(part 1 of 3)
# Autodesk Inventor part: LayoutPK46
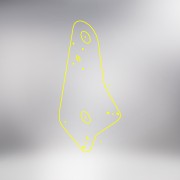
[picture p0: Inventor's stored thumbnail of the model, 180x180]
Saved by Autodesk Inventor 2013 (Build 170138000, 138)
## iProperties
Created: 2012-02
Part Number: LayoutPK46
Material: Generic
Document SubType Name: Modeling
Designer: Daniel Graham
Density: 1 g/cm^3
Author: Daniel Graham
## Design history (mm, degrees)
node "Blocks"
  sketch "_Closed"
    geometry: L1 (-25.4, 4.233)-(0, 0); L2 (0, 0)-(-25.4, -4.233); L3 (-25.4, 4.233)-(-25.4, -4.233); L4 (0, 0)-(-25.4, 0); 1 further point
    constraints: 8 end point, 1 midpoint, 1 perpendicular
  sketch "DatumFilled45"
    geometry: L1 (0, 25.4)-(0, -25.4); L2 (0, -25.4)-(-25.4, 0); L3 (-25.4, 0)-(0, 25.4); L4 (0, 25.4)-(0, -25.4); L5 (0, -25.4)-(0, 25.4); L6 (0, 25.4)-(-25.4, 0); L7 (-25.4, 0)-(0, 25.4); 1 further point
    constraints: 14 end point, 1 perpendicular
  sketch "Filled-1"
    geometry: L1 (-25.4, 0)-(0, 0); L2 (-25.4, -2.527)-(0, 0); L3 (0, 0)-(-25.4, 2.527); L4 (-25.4, 2.527)-(-25.4, -2.527); L5 (-25.4, -2.527)-(0, 0); L6 (0, 0)-(-25.4, -2.527); L7 (-25.4, -2.527)-(-25.4, 2.527); L8 (-25.4, 2.527)-(-25.4, -2.527); L9 (-25.4, -2.527)-(0, 0); L10 (0, 0)-(-25.4, 2.527); L11 (-25.4, 2.527)-(-25.4, -2.527); 1 further point
    constraints: 22 end point, 4 midpoint, 1 perpendicular
  sketch "Borders Default Border"
    geometry: L1 (19.05, 12.7)-(19.05, 419.1); L2 (19.05, 419.1)-(539.75, 419.1); L3 (539.75, 419.1)-(539.75, 12.7); L4 (539.75, 12.7)-(19.05, 12.7); L5 (279.4, 6.35)-(279.4, 12.7); L6 (279.4, 12.7)-(277.2, 8.89); L7 (277.2, 8.89)-(281.6, 8.89); L8 (281.6, 8.89)-(279.4, 12.7); L9 (279.4, 425.45)-(279.4, 419.1); L10 (279.4, 419.1)-(277.2, 422.91); L11 (277.2, 422.91)-(281.6, 422.91); L12 (281.6, 422.91)-(279.4, 419.1); L13 (12.7, 215.9)-(19.05, 215.9); L14 (19.05, 215.9)-(15.24, 218.1); L15 (15.24, 218.1)-(15.24, 213.7); L16 (15.24, 213.7)-(19.05, 215.9); L17 (546.1, 215.9)-(539.75, 215.9); L18 (539.75, 215.9)-(543.56, 218.1); L19 (543.56, 218.1)-(543.56, 213.7); L20 (543.56, 213.7)-(539.75, 215.9); L21 (139.7, 12.7)-(139.7, 8.636); L22 (139.7, 419.1)-(139.7, 423.164); L23 (419.1, 12.7)-(419.1, 8.636); L24 (419.1, 419.1)-(419.1, 423.164); L25 (19.05, 107.95)-(14.986, 107.95); L26 (539.75, 107.95)-(543.814, 107.95); L27 (19.05, 323.85)-(14.986, 323.85); L28 (539.75, 323.85)-(543.814, 323.85); 17 further points
    constraints: 56 end point, 14 parallel, 11 perpendicular, 8 point on line, 4 midpoint, 16 other
  sketch "GENAXEH"
    geometry: L1 (-25.4, 0)-(25.4, 0); 1 further point
    constraints: 2 end point
  sketch "Weldment"
    geometry: L1 (-362.49, 605.558)-(-187.308, 59.988); L2 (-48.402, -559.479)-(-89.17, -792.346); L3 (104.596, -840)-(155.018, -682.036); L4 (176.996, -25.915)-(5.037, 246.17); L5 (5.037, 246.17)-(-175.085, 674.867); L6 (-187.308, 59.988)-(-152.339, -48.916); L7 (-104.241, -121.383)-(-75.352, -146.192); L8 (-8.649, -332.41)-(-48.402, -559.479); L9 (155.018, -682.036)-(230.654, -445.083); L10 (-57.997, -88.254)-(-54.949, -85.206); L11 (-57.997, -85.206)-(-54.949, -88.254); C1 r 75 at (0, 0); C2 r 87 at (0, 0); C3 r 45 at (-267.278, 636.131); C4 r 45 at (9.332, -809.591); C5 r 1.524 at (-56.473, -86.73); A1 r 100 centre (-267.278, 636.131) between (-175.085, 674.867) and (-362.49, 605.558); A2 r 100 centre (9.332, -809.591) between (-89.17, -792.346) and (104.596, -840); A3 r 500 centre (-245.668, -293.04) between (250.28, -356.567) and (176.996, -25.915); A4 r 160 centre (0, 0) between (-152.339, -48.916) and (-104.241, -121.383); A5 r 200 centre (-205.653, -297.921) between (-8.649, -332.41) and (-75.352, -146.192); A6 r 500 centre (-245.668, -293.04) between (230.654, -445.083) and (250.28, -356.567); 1 further point
    constraints: 22 end point, 14 tangent, 12 point on circle, 11 centre point, 4 concentric, 3 equal radius, 1 perpendicular
  sketch "Connector"
    geometry: L1 (157.164, 27.531)-(232.989, 74.957); L2 (483.604, 231.708)-(512.662, 249.882); L3 (76.449, -64.463)-(145.454, 17.372); L4 (449.028, 351.621)-(398.755, 320.177); L5 (509.104, 419.139)-(460.738, 361.78); L6 (526.921, 255.966)-(571.21, 267.162); L7 (232.989, 74.957)-(483.604, 231.708); L8 (398.755, 320.177)-(93.53, 129.27); L9 (529.743, 443.615)-(509.104, 419.139); L10 (79.271, 123.186)-(-24.509, 96.95); L11 (571.21, 267.162)-(630.701, 282.202); L12 (302.321, 205.82)-(305.369, 208.868); L13 (302.321, 208.868)-(305.369, 205.82); C1 r 45 at (0, 0); C2 r 45 at (606.192, 379.152); C3 r 1.524 at (303.845, 207.344); A1 r 50 centre (539.176, 207.491) between (526.921, 255.966) and (512.662, 249.882); A2 r 50 centre (183.678, -14.86) between (157.164, 27.531) and (145.454, 17.372); A3 r 50 centre (422.514, 394.012) between (449.028, 351.621) and (460.738, 361.78); A4 r 50 centre (67.016, 171.661) between (79.271, 123.186) and (93.53, 129.27); A5 r 100 centre (606.192, 379.152) between (630.701, 282.202) and (529.743, 443.615); A6 r 100 centre (0, 0) between (-24.509, 96.95) and (76.449, -64.463); 1 further point
    constraints: 26 end point, 16 tangent, 12 point on circle, 9 centre point, 5 equal radius, 3 parallel, 2 concentric, 1 collinear, 1 perpendicular
  sketch "Base"
    geometry: L1 (278.529, -481.687)-(299.453, -447.453); L2 (295.917, -416.857)-(172.052, -291.319); L3 (95.022, -681.286)-(272.857, -489.184); L4 (108.329, 19.101)-(158.403, -264.884); L5 (-225.117, -660.979)-(-108.413, 18.617); L6 (-225.235, -722.613)-(-225.117, -660.979); L7 (-198.661, -766.881)-(-24.713, -859.13); L8 (3.19, -856.093)-(33.762, -830.109); L9 (48.097, -808.832)-(84.242, -699.551); L10 (37.419, -377.546)-(40.467, -374.498); L11 (37.419, -374.498)-(40.467, -377.546); C1 r 40 at (0, -600); C2 r 40 at (0, 0); C3 r 1.524 at (38.943, -376.022); A1 r 47.5 centre (238, -456.916) between (272.857, -489.184) and (278.529, -481.687); A2 r 25 centre (278.122, -434.416) between (299.453, -447.453) and (295.917, -416.857); A3 r 50 centre (207.644, -256.202) between (158.403, -264.884) and (172.052, -291.319); A4 r 50 centre (-175.235, -722.709) between (-225.235, -722.613) and (-198.661, -766.881); A5 r 50 centre (131.713, -715.252) between (95.022, -681.286) and (84.242, -699.551); A6 r 110 centre (0, 0) between (108.329, 19.101) and (-108.413, 18.617); A7 r 25 centre (-13, -837.043) between (-24.713, -859.13) and (3.19, -856.093); A8 r 47.5 centre (3, -793.916) between (33.762, -830.109) and (48.097, -808.832); 1 further point
    constraints: 22 end point, 16 point on circle, 16 tangent, 11 centre point, 5 equal radius, 1 concentric, 1 perpendicular
  sketch "CenterSpan"
    geometry: L1 (273.969, -185.044)-(234.974, -284.945); L2 (36.362, 93.155)-(259.933, 5.887); L3 (12.317, -103.462)-(-16.542, -98.622); L4 (180.829, -183.299)-(-38.18, -97.812); L5 (437.598, -26.22)-(296.603, -162.709); L6 (-23.266, 102.39)-(214.339, 156.38); L7 (495.815, 30.136)-(437.598, -26.22); L8 (214.339, 156.38)-(404.104, 199.5); L9 (110.262, -93.996)-(113.31, -90.948); L10 (110.262, -90.948)-(113.31, -93.996); C1 r 82 at (0, 0); C2 r 82 at (223.572, -87.267); C3 r 50 at (426.262, 101.986); C4 r 58.472 at (158.121, -254.946); C5 r 1.524 at (111.786, -92.472); A1 r 90 centre (-2.571, -192.223) between (81.268, -224.948) and (12.317, -103.462); A2 r 60 centre (329.862, -206.861) between (290.003, -162.013) and (273.969, -185.044); A3 r 100 centre (223.572, -87.267) between (290.003, -162.013) and (259.933, 5.887); A4 r 100 centre (0, 0) between (36.362, 93.155) and (-16.542, -98.622); A5 r 105 centre (223.572, -87.267) between (189.942, -186.736) and (296.603, -162.709); A6 r 105 centre (0, 0) between (-23.266, 102.39) and (-38.18, -97.812); A7 r 100 centre (426.262, 101.986) between (495.815, 30.136) and (404.104, 199.5); A8 r 82.5 centre (158.121, -254.946) between (81.268, -224.948) and (234.974, -284.945); 1 further point
    constraints: 20 end point, 17 point on circle, 15 tangent, 13 centre point, 6 concentric, 3 equal radius, 3 perpendicular, 1 collinear, 1 point on line
  sketch "Arm"
    geometry: L1 (-25.496, -107.005)-(137.409, -145.82); L2 (2597.068, -901.099)-(2521.421, -896.025); L3 (2257.231, -771.408)-(2076.35, -579.673); L4 (2076.35, -579.673)-(2063.205, -583.463); L5 (2043.846, -578.704)-(1704.981, -254.849); L6 (1379.251, -95.221)-(16.283, 108.788); L7 (137.409, -145.82)-(1374.243, -440.518); L8 (1601.431, -691.827)-(2199.578, -1052.198); L9 (2469.644, -1123.775)-(2592.355, -1120.82); L10 (1293.329, -509.09)-(1296.377, -506.042); L11 (1293.329, -506.042)-(1296.377, -509.09); C1 r 40.528 at (0, 0); C2 r 40.528 at (2589.706, -1010.852); C3 r 1.524 at (1294.853, -507.566); A1 r 400 centre (2548.19, -496.921) between (2482.623, -891.511) and (2521.421, -896.025); A2 r 110 centre (2589.706, -1010.852) between (2597.994, -1120.539) and (2597.068, -901.099); A3 r 400 centre (2548.19, -496.921) between (2257.231, -771.408) and (2482.623, -891.511); A4 r 20 centre (2057.664, -564.246) between (2043.846, -578.704) and (2063.205, -583.463); A5 r 600 centre (1290.432, -688.61) between (1704.981, -254.849) and (1379.251, -95.221); A6 r 70 centre (1358.018, -508.612) between (1423.227, -534.065) and (1374.243, -440.518); A7 r 100 centre (1516.382, -570.427) between (1423.227, -534.065) and (1519.438, -670.38); A8 r 150 centre (1524.023, -820.31) between (1601.431, -691.827) and (1519.438, -670.38); A9 r 500 centre (2457.606, -623.92) between (2199.578, -1052.198) and (2469.644, -1123.775); A10 r 110 centre (0, 0) between (16.283, 108.788) and (-25.496, -107.005); 1 further point
    constraints: 22 end point, 20 point on circle, 17 tangent, 13 centre point, 3 concentric, 2 equal radius, 1 collinear, 1 perpendicular
  sketch "Bucket"
    geometry: 1 further point
  sketch "FrontBucket"
    geometry: L1 (36.508, 713.207)-(-16.797, 670.2); L2 (-16.797, 670.2)-(-101.739, 335.484); L3 (-101.739, 335.484)-(-109.966, 2.719); L4 (8.288, -109.687)-(308.835, -86.978); L5 (308.835, -86.978)-(319.542, -83.051); L6 (19.324, 520.756)-(99.155, 741.781); L7 (99.155, 741.781)-(80.344, 748.575); L8 (80.344, 748.575)-(36.508, 713.207); L9 (1233.625, 258.517)-(1200.234, 261.682); L10 (1200.234, 261.682)-(1143.868, 239.874); L11 (1143.868, 239.874)-(1177.667, 236.867); L12 (1177.667, 236.867)-(1233.625, 258.517); L13 (967.076, 171.475)-(1143.868, 239.874); L14 (1181.276, 227.541)-(976.097, 148.159); L15 (976.097, 148.159)-(967.076, 171.475); L16 (1237.234, 249.191)-(1233.625, 258.517); L17 (1177.667, 236.867)-(1181.276, 227.541); L18 (1181.276, 227.541)-(1237.234, 249.191); L19 (332.219, -99.88)-(327.869, -88.635); L20 (332.219, -99.88)-(340.093, -96.834); L21 (327.869, -88.635)-(326.446, -84.958); L22 (630.662, 15.585)-(695.946, 40.843); L23 (340.093, -96.834)-(630.662, 15.585); L24 (971.406, 160.283)-(964.544, 144.762); L25 (971.406, 160.283)-(969.963, 164.014); L26 (695.946, 40.843)-(690.173, 55.765); L27 (969.963, 164.014)-(690.173, 55.765); L28 (695.946, 40.843)-(964.544, 144.762); L29 (271.723, 1081.905)-(246.908, 1104.472); L30 (246.908, 1104.472)-(15.69, 814.708); L31 (11.012, 759.335)-(43.462, 700.624); L32 (47.21, 660.849)-(-0.759, 514.651); L33 (556.412, -14.214)-(696.307, 39.911); L34 (696.307, 39.911)-(695.946, 40.843); L35 (594.585, 649.257)-(271.723, 1081.905); L36 (459.694, 596.673)-(459.353, 596.937); L37 (459.353, 596.937)-(498.23, 611.978); L38 (1112.062, 227.901)-(576.694, 642.28); L39 (995.062, 182.294)-(998.041, 183.455); L40 (499.228, 612.083)-(459.694, 596.673); L41 (459.694, 596.673)-(526.939, 544.624); L42 (606.946, 482.699)-(686.952, 420.773); L43 (766.958, 358.848)-(846.965, 296.922); L44 (926.971, 234.997)-(985.819, 189.448); L45 (995.055, 182.3)-(995.062, 182.294); L46 (998.041, 183.455)-(1130.882, 235.237); L47 (985.819, 189.448)-(995.055, 182.3); L48 (1130.882, 235.237)-(595.514, 649.616); C1 r 60 at (0, 0); C2 r 85 at (-189.66, 366.918); C3 r 25 at (54.772, 783.522); C4 r 62.5 at (-189.66, 366.918); A1 r 110 centre (0, 0) between (-109.966, 2.719) and (8.288, -109.687); A2 r 408 centre (403.06, 382.155) between (19.324, 520.756) and (16.94, 513.969); A3 r 50 centre (54.772, 783.522) between (15.69, 814.708) and (11.012, 759.335); A4 r 50 centre (-0.298, 676.437) between (47.21, 660.849) and (43.462, 700.624); A5 r 425 centre (403.06, 382.155) between (-0.759, 514.651) and (556.412, -14.214); 1 further point
    constraints: 96 end point, 17 parallel, 12 tangent, 10 point on circle, 9 centre point, 7 collinear, 6 perpendicular, 6 point on line, 4 concentric, 1 equal radius
  sketch "Borders Default Border_9.00X"
    geometry: L1 (171.45, 114.3)-(171.45, 3771.9); L2 (171.45, 3771.9)-(4857.749, 3771.9); L3 (4857.749, 3771.9)-(4857.749, 114.3); L4 (4857.749, 114.3)-(171.45, 114.3); L5 (2514.6, 57.15)-(2514.6, 114.3); L6 (2514.6, 114.3)-(2494.803, 80.01); L7 (2494.803, 80.01)-(2534.397, 80.01); L8 (2534.397, 80.01)-(2514.6, 114.3); L9 (2514.6, 3829.05)-(2514.6, 3771.9); L10 (2514.6, 3771.9)-(2494.803, 3806.19); L11 (2494.803, 3806.19)-(2534.397, 3806.19); L12 (2534.397, 3806.19)-(2514.6, 3771.9); L13 (114.3, 1943.1)-(171.45, 1943.1); L14 (171.45, 1943.1)-(137.16, 1962.897); L15 (137.16, 1962.897)-(137.16, 1923.303); L16 (137.16, 1923.303)-(171.45, 1943.1); L17 (4914.9, 1943.099)-(4857.749, 1943.099); L18 (4857.749, 1943.099)-(4892.04, 1962.897); L19 (4892.04, 1962.897)-(4892.04, 1923.302); L20 (4892.04, 1923.302)-(4857.749, 1943.099); L21 (1257.3, 114.3)-(1257.3, 77.724); L22 (1257.3, 3771.9)-(1257.3, 3808.476); L23 (3771.9, 114.3)-(3771.9, 77.724); L24 (3771.9, 3771.9)-(3771.9, 3808.476); L25 (171.45, 971.55)-(134.874, 971.55); L26 (4857.749, 971.549)-(4894.326, 971.549); L27 (171.45, 2914.65)-(134.874, 2914.65); L28 (4857.749, 2914.649)-(4894.326, 2914.649); 17 further points
    constraints: 56 end point, 14 parallel, 11 perpendicular, 8 point on line, 4 midpoint, 16 other
  sketch "_Closed_1"
    geometry: L1 (-25.4, 4.233)-(0, 0); L2 (0, 0)-(-25.4, -4.233); L3 (-25.4, 4.233)-(-25.4, -4.233); L4 (0, 0)-(-25.4, 0); 1 further point
    constraints: 8 end point, 1 midpoint
  sketch "DatumFilled45_1"
    geometry: L1 (0, 25.4)-(0, -25.4); L2 (0, -25.4)-(-25.4, 0); L3 (-25.4, 0)-(0, 25.4); L4 (0, 25.4)-(0, -25.4); L5 (0, -25.4)-(0, 25.4); L6 (0, 25.4)-(-25.4, 0); L7 (-25.4, 0)-(0, 25.4); 1 further point
    constraints: 14 end point
  sketch "Filled-1_1"
    geometry: L1 (-25.4, 0)-(0, 0); L2 (-25.4, -2.527)-(0, 0); L3 (0, 0)-(-25.4, 2.527); L4 (-25.4, 2.527)-(-25.4, -2.527); L5 (-25.4, -2.527)-(0, 0); L6 (0, 0)-(-25.4, -2.527); L7 (-25.4, -2.527)-(-25.4, 2.527); L8 (-25.4, 2.527)-(-25.4, -2.527); L9 (-25.4, -2.527)-(0, 0); L10 (0, 0)-(-25.4, 2.527); L11 (-25.4, 2.527)-(-25.4, -2.527); 1 further point
    constraints: 22 end point, 4 midpoint
  sketch "Borders Default Border_1"
    geometry: L1 (19.05, 12.7)-(19.05, 419.1); L2 (19.05, 419.1)-(539.75, 419.1); L3 (539.75, 419.1)-(539.75, 12.7); L4 (539.75, 12.7)-(19.05, 12.7); L5 (279.4, 6.35)-(279.4, 12.7); L6 (279.4, 12.7)-(277.2, 8.89); L7 (277.2, 8.89)-(281.6, 8.89); L8 (281.6, 8.89)-(279.4, 12.7); L9 (279.4, 425.45)-(279.4, 419.1); L10 (279.4, 419.1)-(277.2, 422.91); L11 (277.2, 422.91)-(281.6, 422.91); L12 (281.6, 422.91)-(279.4, 419.1); L13 (12.7, 215.9)-(19.05, 215.9); L14 (19.05, 215.9)-(15.24, 218.1); L15 (15.24, 218.1)-(15.24, 213.7); L16 (15.24, 213.7)-(19.05, 215.9); L17 (546.1, 215.9)-(539.75, 215.9); L18 (539.75, 215.9)-(543.56, 218.1); L19 (543.56, 218.1)-(543.56, 213.7); L20 (543.56, 213.7)-(539.75, 215.9); L21 (139.7, 12.7)-(139.7, 8.636); L22 (139.7, 419.1)-(139.7, 423.164); L23 (419.1, 12.7)-(419.1, 8.636); L24 (419.1, 419.1)-(419.1, 423.164); L25 (19.05, 107.95)-(14.986, 107.95); L26 (539.75, 107.95)-(543.814, 107.95); L27 (19.05, 323.85)-(14.986, 323.85); L28 (539.75, 323.85)-(543.814, 323.85); 17 further points
    constraints: 56 end point, 8 point on line, 4 midpoint, 16 other
  sketch "GENAXEH_1"
    geometry: L1 (-25.4, 0)-(25.4, 0); 1 further point
    constraints: 2 end point
  sketch "Weldment_1"
    geometry: L1 (-362.49, 605.558)-(-187.308, 59.988); L2 (-48.402, -559.479)-(-89.17, -792.346); L3 (104.596, -840)-(155.018, -682.036); L4 (176.996, -25.915)-(5.037, 246.17); L5 (5.037, 246.17)-(-175.085, 674.867); L6 (-187.308, 59.988)-(-152.339, -48.916); L7 (-104.241, -121.383)-(-75.352, -146.192); L8 (-8.649, -332.41)-(-48.402, -559.479); L9 (155.018, -682.036)-(230.654, -445.083); L10 (-57.997, -88.254)-(-54.949, -85.206); L11 (-57.997, -85.206)-(-54.949, -88.254); C1 r 75 at (0, 0); C2 r 87 at (0, 0); C3 r 45 at (-267.278, 636.131); C4 r 45 at (9.332, -809.591); C5 r 1.524 at (-56.473, -86.73); A1 r 100 centre (-267.278, 636.131) between (-175.085, 674.867) and (-362.49, 605.558); A2 r 100 centre (9.332, -809.591) between (-89.17, -792.346) and (104.596, -840); A3 r 500 centre (-245.668, -293.04) between (250.28, -356.567) and (176.996, -25.915); A4 r 160 centre (0, 0) between (-152.339, -48.916) and (-104.241, -121.383); A5 r 200 centre (-205.653, -297.921) between (-8.649, -332.41) and (-75.352, -146.192); A6 r 500 centre (-245.668, -293.04) between (230.654, -445.083) and (250.28, -356.567); 1 further point
    constraints: 22 end point, 12 point on circle, 11 centre point
  sketch "Connector_1"
    geometry: L1 (157.164, 27.531)-(232.989, 74.957); L2 (483.604, 231.708)-(512.662, 249.882); L3 (76.449, -64.463)-(145.454, 17.372); L4 (449.028, 351.621)-(398.755, 320.177); L5 (509.104, 419.139)-(460.738, 361.78); L6 (526.921, 255.966)-(571.21, 267.162); L7 (232.989, 74.957)-(483.604, 231.708); L8 (398.755, 320.177)-(93.53, 129.27); L9 (529.743, 443.615)-(509.104, 419.139); L10 (79.271, 123.186)-(-24.509, 96.95); L11 (571.21, 267.162)-(630.701, 282.202); L12 (302.321, 205.82)-(305.369, 208.868); L13 (302.321, 208.868)-(305.369, 205.82); C1 r 45 at (0, 0); C2 r 45 at (606.192, 379.152); C3 r 1.524 at (303.845, 207.344); A1 r 50 centre (539.176, 207.491) between (526.921, 255.966) and (512.662, 249.882); A2 r 50 centre (183.678, -14.86) between (157.164, 27.531) and (145.454, 17.372); A3 r 50 centre (422.514, 394.012) between (449.028, 351.621) and (460.738, 361.78); A4 r 50 centre (67.016, 171.661) between (79.271, 123.186) and (93.53, 129.27); A5 r 100 centre (606.192, 379.152) between (630.701, 282.202) and (529.743, 443.615); A6 r 100 centre (0, 0) between (-24.509, 96.95) and (76.449, -64.463); 1 further point
    constraints: 26 end point, 12 point on circle, 9 centre point
  sketch "Base_1"
    geometry: L1 (278.529, -481.687)-(299.453, -447.453); L2 (295.917, -416.857)-(172.052, -291.319); L3 (95.022, -681.286)-(272.857, -489.184); L4 (108.329, 19.101)-(158.403, -264.884); L5 (-225.117, -660.979)-(-108.413, 18.617); L6 (-225.235, -722.613)-(-225.117, -660.979); L7 (-198.661, -766.881)-(-24.713, -859.13); L8 (3.19, -856.093)-(33.762, -830.109); L9 (48.097, -808.832)-(84.242, -699.551); L10 (37.419, -377.546)-(40.467, -374.498); L11 (37.419, -374.498)-(40.467, -377.546); C1 r 40 at (0, -600); C2 r 40 at (0, 0); C3 r 1.524 at (38.943, -376.022); A1 r 47.5 centre (238, -456.916) between (272.857, -489.184) and (278.529, -481.687); A2 r 25 centre (278.122, -434.416) between (299.453, -447.453) and (295.917, -416.857); A3 r 50 centre (207.644, -256.202) between (158.403, -264.884) and (172.052, -291.319); A4 r 50 centre (-175.235, -722.709) between (-225.235, -722.613) and (-198.661, -766.881); A5 r 50 centre (131.713, -715.252) between (95.022, -681.286) and (84.242, -699.551); A6 r 110 centre (0, 0) between (108.329, 19.101) and (-108.413, 18.617); A7 r 25 centre (-13, -837.043) between (-24.713, -859.13) and (3.19, -856.093); A8 r 47.5 centre (3, -793.916) between (33.762, -830.109) and (48.097, -808.832); 1 further point
    constraints: 22 end point, 16 point on circle, 11 centre point
  sketch "CenterSpan_1"
    geometry: L1 (273.969, -185.044)-(234.974, -284.945); L2 (36.362, 93.155)-(259.933, 5.887); L3 (12.317, -103.462)-(-16.542, -98.622); L4 (180.828, -183.299)-(-38.18, -97.813); L5 (437.598, -26.221)-(296.603, -162.71); L6 (-23.266, 102.39)-(214.339, 156.38); L7 (495.815, 30.136)-(437.598, -26.221); L8 (214.339, 156.38)-(404.104, 199.5); L9 (110.262, -93.996)-(113.31, -90.948); L10 (110.262, -90.948)-(113.31, -93.996); C1 r 82 at (0, 0); C2 r 82 at (223.572, -87.268); C3 r 50 at (426.262, 101.986); C4 r 58.472 at (158.121, -254.947); C5 r 1.524 at (111.786, -92.472); A1 r 90 centre (-2.571, -192.223) between (81.268, -224.948) and (12.317, -103.462); A2 r 60 centre (329.862, -206.861) between (290.003, -162.013) and (273.969, -185.044); A3 r 100 centre (223.572, -87.267) between (290.003, -162.013) and (259.933, 5.887); A4 r 100 centre (0, 0) between (36.362, 93.155) and (-16.542, -98.622); A5 r 105 centre (223.572, -87.268) between (189.942, -186.736) and (296.603, -162.71); A6 r 105 centre (0, 0) between (-23.266, 102.39) and (-38.18, -97.813); A7 r 100 centre (426.262, 101.986) between (495.815, 30.136) and (404.104, 199.5); A8 r 82.5 centre (158.121, -254.946) between (81.268, -224.948) and (234.974, -284.944); 1 further point
    constraints: 20 end point, 17 point on circle, 13 centre point, 1 point on line
  sketch "Arm_1"
    geometry: L1 (-25.496, -107.005)-(137.409, -145.82); L2 (2597.068, -901.099)-(2521.421, -896.025); L3 (2257.231, -771.408)-(2076.35, -579.673); L4 (2076.35, -579.673)-(2063.205, -583.463); L5 (2043.846, -578.704)-(1704.981, -254.849); L6 (1379.251, -95.221)-(16.283, 108.788); L7 (137.409, -145.82)-(1374.243, -440.518); L8 (1601.431, -691.827)-(2199.578, -1052.198); L9 (2469.644, -1123.775)-(2592.355, -1120.82); L10 (1293.329, -509.09)-(1296.377, -506.042); L11 (1293.329, -506.042)-(1296.377, -509.09); C1 r 40.528 at (0, 0); C2 r 40.528 at (2589.706, -1010.852); C3 r 1.524 at (1294.853, -507.566); A1 r 400 centre (2548.19, -496.921) between (2482.623, -891.511) and (2521.421, -896.025); A2 r 110 centre (2589.706, -1010.852) between (2597.994, -1120.539) and (2597.068, -901.099); A3 r 400 centre (2548.19, -496.921) between (2257.231, -771.408) and (2482.623, -891.511); A4 r 20 centre (2057.664, -564.246) between (2043.846, -578.704) and (2063.205, -583.463); A5 r 600 centre (1290.432, -688.61) between (1704.981, -254.849) and (1379.251, -95.221); A6 r 70 centre (1358.018, -508.612) between (1423.227, -534.065) and (1374.243, -440.518); A7 r 100 centre (1516.382, -570.427) between (1423.227, -534.065) and (1519.438, -670.38); A8 r 150 centre (1524.023, -820.31) between (1601.431, -691.827) and (1519.438, -670.38); A9 r 500 centre (2457.606, -623.92) between (2199.578, -1052.198) and (2469.644, -1123.775); A10 r 110 centre (0, 0) between (16.283, 108.788) and (-25.496, -107.005); 1 further point
    constraints: 22 end point, 20 point on circle, 13 centre point
  sketch "Bucket_1"
    geometry: L1 (1144.623, -207.025)-(503.799, -207.025); L2 (963.799, -174.025)-(963.799, -170.025); L3 (503.799, -196.903)-(503.799, -206.906); L4 (503.799, -221.903)-(288.457, -221.903); L5 (288.457, -221.903)-(267.908, -192.554); L6 (513.799, -197.025)-(503.799, -197.025); L7 (1243.799, -187.025)-(1243.799, -177.025); L8 (963.799, -187.025)-(963.799, -162.025); L9 (1144.623, -187.025)-(963.799, -187.025); L10 (963.799, -162.025)-(1213.799, -162.025); L11 (1243.799, -177.025)-(1213.799, -162.025); L12 (787.944, 394.043)-(1129.277, -162.025); L13 (284.259, 704.207)-(293.142, 639.189); L14 (628.799, 940.975)-(308.602, 754.162); L15 (-31.849, -105.289)-(98.676, -144.771); L16 (-48.306, 170.395)-(-101.577, 42.215); L17 (226.161, 631.111)-(211.811, 610.911); L18 (291.393, 651.987)-(226.161, 631.111); L19 (-139.649, 366.255)-(98.676, -144.771); L20 (513.799, -197.025)-(1144.623, -197.025); L21 (513.799, -187.025)-(1144.623, -187.025); L22 (531.254, 866.512)-(201.253, 473.232); L23 (537.781, 858.733)-(208.914, 466.804); L24 (1144.623, -207.025)-(1144.623, -197.025); L25 (1144.623, -197.025)-(1144.623, -187.025); L26 (787.944, 394.043)-(636.196, 915.553); L27 (633.32, 925.44)-(628.799, 940.975); L28 (725.404, 1012.893)-(719.482, 979.31); L29 (735.252, 1011.157)-(729.33, 977.574); L30 (714.634, 972.387)-(531.254, 866.512); L31 (725.404, 1012.893)-(735.252, 1011.157); L32 (1144.623, -187.025)-(1243.799, -187.025); L33 (537.781, 858.733)-(719.634, 963.726); L34 (503.799, -221.903)-(503.799, -206.906); L35 (453.565, -192.554)-(144.85, -192.554); L36 (110.864, -170.904)-(98.676, -144.771); L37 (-78.971, 509.811)-(360.018, 662.44); C1 r 25 at (333.799, 710.975); C2 r 45 at (-44.489, 410.635); A1 r 50 centre (333.799, 710.975) between (308.602, 754.162) and (284.259, 704.207); A2 r 40 centre (0, 0) between (13.62, 37.61) and (37.567, -13.738); A3 r 110 centre (0, 0) between (-101.577, 42.215) and (-31.849, -105.289); A4 r 105 centre (-44.489, 410.635) between (-78.971, 509.811) and (-139.649, 366.255); A5 r 408 centre (513.799, 210.975) between (201.253, 473.232) and (513.799, -197.025); A6 r 398 centre (513.799, 210.975) between (208.914, 466.804) and (513.799, -187.025); A7 r 37.5 centre (144.85, -155.054) between (110.864, -170.904) and (144.85, -192.554); A8 r 10 centre (709.634, 981.047) between (714.634, 972.387) and (719.482, 979.31); A9 r 20 centre (709.634, 981.047) between (719.634, 963.726) and (729.33, 977.574); 1 further point
    constraints: 74 end point, 20 point on circle, 16 point on line, 11 centre point
  sketch "FrontBucket_1"
    geometry: L1 (36.508, 713.207)-(-16.797, 670.2); L2 (-16.797, 670.2)-(-101.739, 335.484); L3 (-101.739, 335.484)-(-109.966, 2.719); L4 (8.288, -109.687)-(308.835, -86.978); L5 (308.835, -86.978)-(319.542, -83.051); L6 (19.324, 520.756)-(99.155, 741.781); L7 (99.155, 741.781)-(80.344, 748.575); L8 (80.344, 748.575)-(36.508, 713.207); L9 (1233.625, 258.517)-(1200.234, 261.682); L10 (1200.234, 261.682)-(1143.868, 239.874); L11 (1143.868, 239.874)-(1177.667, 236.867); L12 (1177.667, 236.867)-(1233.625, 258.517); L13 (967.076, 171.475)-(1143.868, 239.874); L14 (1181.276, 227.541)-(976.097, 148.159); L15 (976.097, 148.159)-(967.076, 171.475); L16 (1237.234, 249.191)-(1233.625, 258.517); L17 (1177.667, 236.867)-(1181.276, 227.541); L18 (1181.276, 227.541)-(1237.234, 249.191); L19 (332.219, -99.88)-(327.869, -88.635); L20 (332.219, -99.88)-(340.093, -96.834); L21 (327.869, -88.635)-(326.446, -84.958); L22 (630.662, 15.585)-(695.946, 40.843); L23 (340.093, -96.834)-(630.662, 15.585); L24 (971.406, 160.283)-(964.544, 144.762); L25 (971.406, 160.283)-(969.963, 164.014); L26 (695.946, 40.843)-(690.173, 55.765); L27 (969.963, 164.014)-(690.173, 55.765); L28 (695.946, 40.843)-(964.544, 144.762); L29 (271.723, 1081.905)-(246.908, 1104.472); L30 (246.908, 1104.472)-(15.69, 814.708); L31 (11.012, 759.335)-(43.462, 700.624); L32 (47.21, 660.849)-(-0.759, 514.651); L33 (556.412, -14.214)-(696.307, 39.911); L34 (696.307, 39.911)-(695.946, 40.843); L35 (594.585, 649.257)-(271.723, 1081.905); L36 (459.694, 596.673)-(459.353, 596.937); L37 (459.353, 596.937)-(498.23, 611.978); L38 (1112.062, 227.901)-(576.694, 642.28); L39 (995.062, 182.294)-(998.041, 183.455); L40 (499.228, 612.083)-(459.694, 596.673); L41 (459.694, 596.673)-(526.939, 544.624); L42 (606.946, 482.699)-(686.952, 420.773); L43 (766.958, 358.848)-(846.965, 296.922); L44 (926.971, 234.997)-(985.819, 189.448); L45 (995.055, 182.3)-(995.062, 182.294); L46 (998.041, 183.455)-(1130.882, 235.237); L47 (985.819, 189.448)-(995.055, 182.3); L48 (1130.882, 235.237)-(595.514, 649.616); C1 r 60 at (0, 0); C2 r 85 at (-189.66, 366.918); C3 r 25 at (54.772, 783.522); C4 r 62.5 at (-189.66, 366.918); A1 r 110 centre (0, 0) between (-109.966, 2.719) and (8.288, -109.687); A2 r 408 centre (403.06, 382.155) between (19.324, 520.756) and (16.94, 513.969); A3 r 50 centre (54.772, 783.522) between (15.69, 814.708) and (11.012, 759.335); A4 r 50 centre (-0.298, 676.437) between (47.21, 660.849) and (43.462, 700.624); A5 r 425 centre (403.06, 382.155) between (-0.759, 514.651) and (556.412, -14.214); 1 further point
    constraints: 96 end point, 10 point on circle, 9 centre point, 6 point on line
  sketch "A$C70327705"
    geometry: L1 (1293.342, 14.877)-(652.519, 14.877); L2 (1112.519, 47.877)-(1112.519, 51.877); L3 (652.519, 25)-(652.519, 14.997); L4 (652.519, 0)-(437.177, 0); L5 (437.177, 0)-(416.627, 29.348); L6 (662.519, 24.877)-(652.519, 24.877); L7 (1392.519, 34.877)-(1392.519, 44.877); L8 (1112.519, 34.877)-(1112.519, 59.877); L9 (1293.342, 34.877)-(1112.519, 34.877); L10 (1112.519, 59.877)-(1362.519, 59.877); L11 (1392.519, 44.877)-(1362.519, 59.877); L12 (936.663, 615.946)-(1277.997, 59.877); L13 (432.979, 926.11)-(441.861, 861.091); L14 (777.519, 1162.877)-(457.322, 976.064); L15 (116.871, 116.614)-(247.396, 77.132); L16 (100.413, 392.297)-(47.142, 264.117); L17 (374.881, 853.013)-(360.531, 832.814); L18 (440.113, 873.889)-(374.881, 853.013); L19 (9.07, 588.157)-(247.396, 77.132); L20 (662.519, 24.877)-(1293.342, 24.877); L21 (662.519, 34.877)-(1293.342, 34.877); L22 (679.974, 1088.415)-(349.973, 695.135); L23 (686.501, 1080.636)-(357.633, 688.707); L24 (1293.342, 14.877)-(1293.342, 24.877); L25 (1293.342, 24.877)-(1293.342, 34.877); L26 (936.663, 615.946)-(784.916, 1137.456); L27 (782.039, 1147.342)-(777.519, 1162.877); L28 (874.123, 1234.796)-(868.202, 1201.213); L29 (883.971, 1233.059)-(878.05, 1199.476); L30 (863.354, 1194.289)-(679.974, 1088.415); L31 (874.123, 1234.796)-(883.971, 1233.059); L32 (1293.342, 34.877)-(1392.519, 34.877); L33 (686.501, 1080.636)-(868.354, 1185.629); L34 (652.519, 0)-(652.519, 14.997); L35 (602.285, 29.348)-(293.569, 29.348); L36 (259.584, 50.998)-(247.396, 77.132); L37 (69.748, 731.714)-(508.737, 884.343); C1 r 25 at (482.519, 932.877); C2 r 45 at (104.231, 632.537); A1 r 50 centre (482.519, 932.877) between (457.322, 976.064) and (432.979, 926.11); A2 r 40 centre (148.72, 221.902) between (162.34, 259.512) and (186.286, 208.165); A3 r 110 centre (148.72, 221.902) between (47.142, 264.117) and (116.871, 116.614); A4 r 105 centre (104.231, 632.537) between (69.748, 731.714) and (9.07, 588.157); A5 r 408 centre (662.519, 432.877) between (349.973, 695.135) and (662.519, 24.877); A6 r 398 centre (662.519, 432.877) between (357.633, 688.707) and (662.519, 34.877); A7 r 37.5 centre (293.569, 66.848) between (259.584, 50.998) and (293.569, 29.348); A8 r 10 centre (858.354, 1202.949) between (863.354, 1194.289) and (868.202, 1201.213); A9 r 20 centre (858.354, 1202.949) between (868.354, 1185.629) and (878.05, 1199.476); 1 further point
    constraints: 74 end point, 20 point on circle, 16 point on line, 11 centre point
  sketch "A$C60B60B97"
    geometry: 1 further point
  sketch "Borders Default Border_9.00X_1"
    geometry: L1 (171.45, 114.3)-(171.45, 3771.9); L2 (171.45, 3771.9)-(4857.75, 3771.9); L3 (4857.75, 3771.9)-(4857.75, 114.3); L4 (4857.75, 114.3)-(171.45, 114.3); L5 (2514.6, 57.15)-(2514.6, 114.3); L6 (2514.6, 114.3)-(2494.803, 80.01); L7 (2494.803, 80.01)-(2534.397, 80.01); L8 (2534.397, 80.01)-(2514.6, 114.3); L9 (2514.6, 3829.05)-(2514.6, 3771.9); L10 (2514.6, 3771.9)-(2494.803, 3806.19); L11 (2494.803, 3806.19)-(2534.397, 3806.19); L12 (2534.397, 3806.19)-(2514.6, 3771.9); L13 (114.3, 1943.1)-(171.45, 1943.1); L14 (171.45, 1943.1)-(137.16, 1962.897); L15 (137.16, 1962.897)-(137.16, 1923.303); L16 (137.16, 1923.303)-(171.45, 1943.1); L17 (4914.9, 1943.1)-(4857.75, 1943.1); L18 (4857.75, 1943.1)-(4892.04, 1962.897); L19 (4892.04, 1962.897)-(4892.04, 1923.303); L20 (4892.04, 1923.303)-(4857.75, 1943.1); L21 (1257.3, 114.3)-(1257.3, 77.724); L22 (1257.3, 3771.9)-(1257.3, 3808.476); L23 (3771.9, 114.3)-(3771.9, 77.724); L24 (3771.9, 3771.9)-(3771.9, 3808.476); L25 (171.45, 971.55)-(134.874, 971.55); L26 (4857.75, 971.55)-(4894.326, 971.55); L27 (171.45, 2914.65)-(134.874, 2914.65); L28 (4857.75, 2914.65)-(4894.326, 2914.65); 17 further points
    constraints: 56 end point, 8 point on line, 4 midpoint, 16 other
  sketch "_Closed_2"
    geometry: L1 (-25.4, 4.233)-(0, 0); L2 (0, 0)-(-25.4, -4.233); L3 (-25.4, 4.233)-(-25.4, -4.233); L4 (0, 0)-(-25.4, 0); 1 further point
    constraints: 8 end point, 1 midpoint
  sketch "DatumFilled45_2"
    geometry: L1 (0, 25.4)-(0, -25.4); L2 (0, -25.4)-(-25.4, 0); L3 (-25.4, 0)-(0, 25.4); L4 (0, 25.4)-(0, -25.4); L5 (0, -25.4)-(0, 25.4); L6 (0, 25.4)-(-25.4, 0); L7 (-25.4, 0)-(0, 25.4); 1 further point
    constraints: 14 end point
  sketch "Filled-1_2"
    geometry: L1 (-25.4, 0)-(0, 0); L2 (-25.4, -2.527)-(0, 0); L3 (0, 0)-(-25.4, 2.527); L4 (-25.4, 2.527)-(-25.4, -2.527); L5 (-25.4, -2.527)-(0, 0); L6 (0, 0)-(-25.4, -2.527); L7 (-25.4, -2.527)-(-25.4, 2.527); L8 (-25.4, 2.527)-(-25.4, -2.527); L9 (-25.4, -2.527)-(0, 0); L10 (0, 0)-(-25.4, 2.527); L11 (-25.4, 2.527)-(-25.4, -2.527); 1 further point
    constraints: 22 end point, 4 midpoint
  sketch "Borders Default Border_2"
    geometry: L1 (19.05, 12.7)-(19.05, 419.1); L2 (19.05, 419.1)-(539.75, 419.1); L3 (539.75, 419.1)-(539.75, 12.7); L4 (539.75, 12.7)-(19.05, 12.7); L5 (279.4, 6.35)-(279.4, 12.7); L6 (279.4, 12.7)-(277.2, 8.89); L7 (277.2, 8.89)-(281.6, 8.89); L8 (281.6, 8.89)-(279.4, 12.7); L9 (279.4, 425.45)-(279.4, 419.1); L10 (279.4, 419.1)-(277.2, 422.91); L11 (277.2, 422.91)-(281.6, 422.91); L12 (281.6, 422.91)-(279.4, 419.1); L13 (12.7, 215.9)-(19.05, 215.9); L14 (19.05, 215.9)-(15.24, 218.1); L15 (15.24, 218.1)-(15.24, 213.7); L16 (15.24, 213.7)-(19.05, 215.9); L17 (546.1, 215.9)-(539.75, 215.9); L18 (539.75, 215.9)-(543.56, 218.1); L19 (543.56, 218.1)-(543.56, 213.7); L20 (543.56, 213.7)-(539.75, 215.9); L21 (139.7, 12.7)-(139.7, 8.636); L22 (139.7, 419.1)-(139.7, 423.164); L23 (419.1, 12.7)-(419.1, 8.636); L24 (419.1, 419.1)-(419.1, 423.164); L25 (19.05, 107.95)-(14.986, 107.95); L26 (539.75, 107.95)-(543.814, 107.95); L27 (19.05, 323.85)-(14.986, 323.85); L28 (539.75, 323.85)-(543.814, 323.85); 17 further points
    constraints: 56 end point, 8 point on line, 4 midpoint, 16 other
  sketch "GENAXEH_2"
    geometry: L1 (-25.4, 0)-(25.4, 0); 1 further point
    constraints: 2 end point
  sketch "Weldment_2"
    geometry: L1 (-362.49, 605.558)-(-187.308, 59.988); L2 (-48.402, -559.479)-(-89.17, -792.346); L3 (104.596, -840)-(155.018, -682.036); L4 (176.996, -25.915)-(5.037, 246.17); L5 (5.037, 246.17)-(-175.085, 674.867); L6 (-187.308, 59.988)-(-152.339, -48.916); L7 (-104.241, -121.383)-(-75.352, -146.192); L8 (-8.649, -332.41)-(-48.402, -559.479); L9 (155.018, -682.036)-(230.654, -445.083); L10 (-57.997, -88.254)-(-54.949, -85.206); L11 (-57.997, -85.206)-(-54.949, -88.254); C1 r 75 at (0, 0); C2 r 87 at (0, 0); C3 r 45 at (-267.278, 636.131); C4 r 45 at (9.332, -809.591); C5 r 1.524 at (-56.473, -86.73); A1 r 100 centre (-267.278, 636.131) between (-175.085, 674.867) and (-362.49, 605.558); A2 r 100 centre (9.332, -809.591) between (-89.17, -792.346) and (104.596, -840); A3 r 500 centre (-245.668, -293.04) between (250.28, -356.567) and (176.996, -25.915); A4 r 160 centre (0, 0) between (-152.339, -48.916) and (-104.241, -121.383); A5 r 200 centre (-205.653, -297.921) between (-8.649, -332.41) and (-75.352, -146.192); A6 r 500 centre (-245.668, -293.04) between (230.654, -445.083) and (250.28, -356.567); 1 further point
    constraints: 22 end point, 12 point on circle, 11 centre point
  sketch "Connector_2"
    geometry: L1 (157.164, 27.531)-(232.989, 74.957); L2 (483.604, 231.708)-(512.662, 249.882); L3 (76.449, -64.463)-(145.454, 17.372); L4 (449.028, 351.621)-(398.755, 320.177); L5 (509.104, 419.139)-(460.738, 361.78); L6 (526.921, 255.966)-(571.21, 267.162); L7 (232.989, 74.957)-(483.604, 231.708); L8 (398.755, 320.177)-(93.53, 129.27); L9 (529.743, 443.615)-(509.104, 419.139); L10 (79.271, 123.186)-(-24.509, 96.95); L11 (571.21, 267.162)-(630.701, 282.202); L12 (302.321, 205.82)-(305.369, 208.868); L13 (302.321, 208.868)-(305.369, 205.82); C1 r 45 at (0, 0); C2 r 45 at (606.192, 379.152); C3 r 1.524 at (303.845, 207.344); A1 r 50 centre (539.176, 207.491) between (526.921, 255.966) and (512.662, 249.882); A2 r 50 centre (183.678, -14.86) between (157.164, 27.531) and (145.454, 17.372); A3 r 50 centre (422.514, 394.012) between (449.028, 351.621) and (460.738, 361.78); A4 r 50 centre (67.016, 171.661) between (79.271, 123.186) and (93.53, 129.27); A5 r 100 centre (606.192, 379.152) between (630.701, 282.202) and (529.743, 443.615); A6 r 100 centre (0, 0) between (-24.509, 96.95) and (76.449, -64.463); 1 further point
    constraints: 26 end point, 12 point on circle, 9 centre point
  sketch "Base_2"
    geometry: L1 (278.529, -481.687)-(299.453, -447.453); L2 (295.917, -416.857)-(172.052, -291.319); L3 (95.022, -681.286)-(272.857, -489.184); L4 (108.329, 19.101)-(158.403, -264.884); L5 (-225.117, -660.979)-(-108.413, 18.617); L6 (-225.235, -722.613)-(-225.117, -660.979); L7 (-198.661, -766.881)-(-24.713, -859.13); L8 (3.19, -856.093)-(33.762, -830.109); L9 (48.097, -808.832)-(84.242, -699.551); L10 (0, 254)-(0, -254); L11 (-254, 0)-(254, 0); L12 (0, -346)-(0, -854); L13 (-254, -600)-(254, -600); L14 (37.419, -377.546)-(40.467, -374.498); L15 (37.419, -374.498)-(40.467, -377.546); C1 r 40 at (0, -600); C2 r 40 at (0, 0); C3 r 1.524 at (38.943, -376.022); A1 r 47.5 centre (238, -456.916) between (272.857, -489.184) and (278.529, -481.687); A2 r 25 centre (278.122, -434.416) between (299.453, -447.453) and (295.917, -416.857); A3 r 50 centre (207.644, -256.202) between (158.403, -264.884) and (172.052, -291.319); A4 r 50 centre (-175.235, -722.709) between (-225.235, -722.613) and (-198.661, -766.881); A5 r 50 centre (131.713, -715.252) between (95.022, -681.286) and (84.242, -699.551); A6 r 110 centre (0, 0) between (108.329, 19.101) and (-108.413, 18.617); A7 r 25 centre (-13, -837.043) between (-24.713, -859.13) and (3.19, -856.093); A8 r 47.5 centre (3, -793.916) between (33.762, -830.109) and (48.097, -808.832); 1 further point
    constraints: 30 end point, 16 point on circle, 11 centre point
  sketch "CenterSpan_2"
    geometry: L1 (273.969, -185.044)-(234.974, -284.945); L2 (36.362, 93.155)-(259.933, 5.887); L3 (12.317, -103.462)-(-16.542, -98.622); L4 (180.828, -183.299)-(-38.18, -97.813); L5 (437.598, -26.221)-(296.603, -162.71); L6 (-23.266, 102.39)-(214.339, 156.38); L7 (495.815, 30.136)-(437.598, -26.221); L8 (214.339, 156.38)-(404.104, 199.5); L9 (110.262, -93.996)-(113.31, -90.948); L10 (110.262, -90.948)-(113.31, -93.996); C1 r 82 at (0, 0); C2 r 82 at (223.572, -87.268); C3 r 50 at (426.262, 101.986); C4 r 58.472 at (158.121, -254.947); C5 r 1.524 at (111.786, -92.472); A1 r 90 centre (-2.571, -192.223) between (81.268, -224.948) and (12.317, -103.462); A2 r 60 centre (329.862, -206.861) between (290.003, -162.013) and (273.969, -185.044); A3 r 100 centre (223.572, -87.267) between (290.003, -162.013) and (259.933, 5.887); A4 r 100 centre (0, 0) between (36.362, 93.155) and (-16.542, -98.622); A5 r 105 centre (223.572, -87.268) between (189.942, -186.736) and (296.603, -162.71); A6 r 105 centre (0, 0) between (-23.266, 102.39) and (-38.18, -97.813); A7 r 100 centre (426.262, 101.986) between (495.815, 30.136) and (404.104, 199.5); A8 r 82.5 centre (158.121, -254.946) between (81.268, -224.948) and (234.974, -284.944); 1 further point
    constraints: 20 end point, 17 point on circle, 13 centre point, 1 point on line
  sketch "Arm_2"
    geometry: L1 (-25.496, -107.005)-(137.409, -145.82); L2 (2597.068, -901.099)-(2521.421, -896.025); L3 (2257.231, -771.408)-(2076.35, -579.673); L4 (2076.35, -579.673)-(2063.205, -583.463); L5 (2043.846, -578.704)-(1704.981, -254.849); L6 (1379.251, -95.221)-(16.283, 108.788); L7 (137.409, -145.82)-(1374.243, -440.518); L8 (1601.431, -691.827)-(2199.578, -1052.198); L9 (2469.644, -1123.775)-(2592.355, -1120.82); L10 (1293.329, -509.09)-(1296.377, -506.042); L11 (1293.329, -506.042)-(1296.377, -509.09); C1 r 40.528 at (0, 0); C2 r 40.528 at (2589.706, -1010.852); C3 r 1.524 at (1294.853, -507.566); A1 r 400 centre (2548.19, -496.921) between (2482.623, -891.511) and (2521.421, -896.025); A2 r 110 centre (2589.706, -1010.852) between (2597.994, -1120.539) and (2597.068, -901.099); A3 r 400 centre (2548.19, -496.921) between (2257.231, -771.408) and (2482.623, -891.511); A4 r 20 centre (2057.664, -564.246) between (2043.846, -578.704) and (2063.205, -583.463); A5 r 600 centre (1290.432, -688.61) between (1704.981, -254.849) and (1379.251, -95.221); A6 r 70 centre (1358.018, -508.612) between (1423.227, -534.065) and (1374.243, -440.518); A7 r 100 centre (1516.382, -570.427) between (1423.227, -534.065) and (1519.438, -670.38); A8 r 150 centre (1524.023, -820.31) between (1601.431, -691.827) and (1519.438, -670.38); A9 r 500 centre (2457.606, -623.92) between (2199.578, -1052.198) and (2469.644, -1123.775); A10 r 110 centre (0, 0) between (16.283, 108.788) and (-25.496, -107.005); 1 further point
    constraints: 22 end point, 20 point on circle, 13 centre point
  sketch "Bucket_2"
    geometry: L1 (1144.623, -207.025)-(503.799, -207.025); L2 (963.799, -174.025)-(963.799, -170.025); L3 (503.799, -196.903)-(503.799, -206.906); L4 (503.799, -221.903)-(288.457, -221.903); L5 (288.457, -221.903)-(267.908, -192.554); L6 (513.799, -197.025)-(503.799, -197.025); L7 (1243.799, -187.025)-(1243.799, -177.025); L8 (963.799, -187.025)-(963.799, -162.025); L9 (1144.623, -187.025)-(963.799, -187.025); L10 (963.799, -162.025)-(1213.799, -162.025); L11 (1243.799, -177.025)-(1213.799, -162.025); L12 (787.944, 394.043)-(1129.277, -162.025); L13 (284.259, 704.207)-(293.142, 639.189); L14 (628.799, 940.975)-(308.602, 754.162); L15 (-31.849, -105.289)-(98.676, -144.771); L16 (-48.306, 170.395)-(-101.577, 42.215); L17 (226.161, 631.111)-(211.811, 610.911); L18 (291.393, 651.987)-(226.161, 631.111); L19 (-139.649, 366.255)-(98.676, -144.771); L20 (513.799, -197.025)-(1144.623, -197.025); L21 (513.799, -187.025)-(1144.623, -187.025); L22 (531.254, 866.512)-(201.253, 473.232); L23 (537.781, 858.733)-(208.914, 466.804); L24 (1144.623, -207.025)-(1144.623, -197.025); L25 (1144.623, -197.025)-(1144.623, -187.025); L26 (787.944, 394.043)-(636.196, 915.553); L27 (633.32, 925.44)-(628.799, 940.975); L28 (725.404, 1012.893)-(719.482, 979.31); L29 (735.252, 1011.157)-(729.33, 977.574); L30 (714.634, 972.387)-(531.254, 866.512); L31 (725.404, 1012.893)-(735.252, 1011.157); L32 (1144.623, -187.025)-(1243.799, -187.025); L33 (537.781, 858.733)-(719.634, 963.726); L34 (503.799, -221.903)-(503.799, -206.906); L35 (453.565, -192.554)-(144.85, -192.554); L36 (110.864, -170.904)-(98.676, -144.771); L37 (-78.971, 509.811)-(360.018, 662.44); C1 r 25 at (333.799, 710.975); C2 r 45 at (-44.489, 410.635); A1 r 50 centre (333.799, 710.975) between (308.602, 754.162) and (284.259, 704.207); A2 r 40 centre (0, 0) between (13.62, 37.61) and (37.567, -13.738); A3 r 110 centre (0, 0) between (-101.577, 42.215) and (-31.849, -105.289); A4 r 105 centre (-44.489, 410.635) between (-78.971, 509.811) and (-139.649, 366.255); A5 r 408 centre (513.799, 210.975) between (201.253, 473.232) and (513.799, -197.025); A6 r 398 centre (513.799, 210.975) between (208.914, 466.804) and (513.799, -187.025); A7 r 37.5 centre (144.85, -155.054) between (110.864, -170.904) and (144.85, -192.554); A8 r 10 centre (709.634, 981.047) between (714.634, 972.387) and (719.482, 979.31); A9 r 20 centre (709.634, 981.047) between (719.634, 963.726) and (729.33, 977.574); 1 further point
    constraints: 74 end point, 20 point on circle, 16 point on line, 11 centre point
  sketch "FrontBucket_2"
    geometry: L1 (36.508, 713.207)-(-16.797, 670.2); L2 (-16.797, 670.2)-(-101.739, 335.484); L3 (-101.739, 335.484)-(-109.966, 2.719); L4 (8.288, -109.687)-(308.835, -86.978); L5 (308.835, -86.978)-(319.542, -83.051); L6 (19.324, 520.756)-(99.155, 741.781); L7 (99.155, 741.781)-(80.344, 748.575); L8 (80.344, 748.575)-(36.508, 713.207); L9 (1233.625, 258.517)-(1200.234, 261.682); L10 (1200.234, 261.682)-(1143.868, 239.874); L11 (1143.868, 239.874)-(1177.667, 236.867); L12 (1177.667, 236.867)-(1233.625, 258.517); L13 (967.076, 171.475)-(1143.868, 239.874); L14 (1181.276, 227.541)-(976.097, 148.159); L15 (976.097, 148.159)-(967.076, 171.475); L16 (1237.234, 249.191)-(1233.625, 258.517); L17 (1177.667, 236.867)-(1181.276, 227.541); L18 (1181.276, 227.541)-(1237.234, 249.191); L19 (332.219, -99.88)-(327.869, -88.635); L20 (332.219, -99.88)-(340.093, -96.834); L21 (327.869, -88.635)-(326.446, -84.958); L22 (630.662, 15.585)-(695.946, 40.843); L23 (340.093, -96.834)-(630.662, 15.585); L24 (971.406, 160.283)-(964.544, 144.762); L25 (971.406, 160.283)-(969.963, 164.014); L26 (695.946, 40.843)-(690.173, 55.765); L27 (969.963, 164.014)-(690.173, 55.765); L28 (695.946, 40.843)-(964.544, 144.762); L29 (271.723, 1081.905)-(246.908, 1104.472); L30 (246.908, 1104.472)-(15.69, 814.708); L31 (11.012, 759.335)-(43.462, 700.624); L32 (47.21, 660.849)-(-0.759, 514.651); L33 (556.412, -14.214)-(696.307, 39.911); L34 (696.307, 39.911)-(695.946, 40.843); L35 (594.585, 649.257)-(271.723, 1081.905); L36 (459.694, 596.673)-(459.353, 596.937); L37 (459.353, 596.937)-(498.23, 611.978); L38 (1112.062, 227.901)-(576.694, 642.28); L39 (995.062, 182.294)-(998.041, 183.455); L40 (499.228, 612.083)-(459.694, 596.673); L41 (459.694, 596.673)-(526.939, 544.624); L42 (606.946, 482.699)-(686.952, 420.773); L43 (766.958, 358.848)-(846.965, 296.922); L44 (926.971, 234.997)-(985.819, 189.448); L45 (995.055, 182.3)-(995.062, 182.294); L46 (998.041, 183.455)-(1130.882, 235.237); L47 (985.819, 189.448)-(995.055, 182.3); L48 (1130.882, 235.237)-(595.514, 649.616); C1 r 60 at (0, 0); C2 r 85 at (-189.66, 366.918); C3 r 25 at (54.772, 783.522); C4 r 62.5 at (-189.66, 366.918); A1 r 110 centre (0, 0) between (-109.966, 2.719) and (8.288, -109.687); A2 r 408 centre (403.06, 382.155) between (19.324, 520.756) and (16.94, 513.969); A3 r 50 centre (54.772, 783.522) between (15.69, 814.708) and (11.012, 759.335); A4 r 50 centre (-0.298, 676.437) between (47.21, 660.849) and (43.462, 700.624); A5 r 425 centre (403.06, 382.155) between (-0.759, 514.651) and (556.412, -14.214); 1 further point
    constraints: 96 end point, 10 point on circle, 9 centre point, 6 point on line
  sketch "A$C70327705_1"
    geometry: L1 (1293.342, 14.877)-(652.519, 14.877); L2 (1112.519, 47.877)-(1112.519, 51.877); L3 (652.519, 25)-(652.519, 14.997); L4 (652.519, 0)-(437.177, 0); L5 (437.177, 0)-(416.627, 29.348); L6 (662.519, 24.877)-(652.519, 24.877); L7 (1392.519, 34.877)-(1392.519, 44.877); L8 (1112.519, 34.877)-(1112.519, 59.877); L9 (1293.342, 34.877)-(1112.519, 34.877); L10 (1112.519, 59.877)-(1362.519, 59.877); L11 (1392.519, 44.877)-(1362.519, 59.877); L12 (936.663, 615.946)-(1277.997, 59.877); L13 (432.979, 926.11)-(441.861, 861.091); L14 (777.519, 1162.877)-(457.322, 976.064); L15 (116.871, 116.614)-(247.396, 77.132); L16 (100.413, 392.297)-(47.142, 264.117); L17 (374.881, 853.013)-(360.531, 832.814); L18 (440.113, 873.889)-(374.881, 853.013); L19 (9.07, 588.157)-(247.396, 77.132); L20 (662.519, 24.877)-(1293.342, 24.877); L21 (662.519, 34.877)-(1293.342, 34.877); L22 (679.974, 1088.415)-(349.973, 695.135); L23 (686.501, 1080.636)-(357.633, 688.707); L24 (1293.342, 14.877)-(1293.342, 24.877); L25 (1293.342, 24.877)-(1293.342, 34.877); L26 (936.663, 615.946)-(784.916, 1137.456); L27 (782.039, 1147.342)-(777.519, 1162.877); L28 (874.123, 1234.796)-(868.202, 1201.213); L29 (883.971, 1233.059)-(878.05, 1199.476); L30 (863.354, 1194.289)-(679.974, 1088.415); L31 (874.123, 1234.796)-(883.971, 1233.059); L32 (1293.342, 34.877)-(1392.519, 34.877); L33 (686.501, 1080.636)-(868.354, 1185.629); L34 (652.519, 0)-(652.519, 14.997); L35 (602.285, 29.348)-(293.569, 29.348); L36 (259.584, 50.998)-(247.396, 77.132); L37 (69.748, 731.714)-(508.737, 884.343); C1 r 25 at (482.519, 932.877); C2 r 45 at (104.231, 632.537); A1 r 50 centre (482.519, 932.877) between (457.322, 976.064) and (432.979, 926.11); A2 r 40 centre (148.72, 221.902) between (162.34, 259.512) and (186.286, 208.165); A3 r 110 centre (148.72, 221.902) between (47.142, 264.117) and (116.871, 116.614); A4 r 105 centre (104.231, 632.537) between (69.748, 731.714) and (9.07, 588.157); A5 r 408 centre (662.519, 432.877) between (349.973, 695.135) and (662.519, 24.877); A6 r 398 centre (662.519, 432.877) between (357.633, 688.707) and (662.519, 34.877); A7 r 37.5 centre (293.569, 66.848) between (259.584, 50.998) and (293.569, 29.348); A8 r 10 centre (858.354, 1202.949) between (863.354, 1194.289) and (868.202, 1201.213); A9 r 20 centre (858.354, 1202.949) between (868.354, 1185.629) and (878.05, 1199.476); 1 further point
    constraints: 74 end point, 20 point on circle, 16 point on line, 11 centre point
  sketch "A$C60B60B97_1"
    geometry: 1 further point
  sketch "Borders Default Border_9.00X_2"
    geometry: L1 (171.45, 114.3)-(171.45, 3771.9); L2 (171.45, 3771.9)-(4857.75, 3771.9); L3 (4857.75, 3771.9)-(4857.75, 114.3); L4 (4857.75, 114.3)-(171.45, 114.3); L5 (2514.6, 57.15)-(2514.6, 114.3); L6 (2514.6, 114.3)-(2494.803, 80.01); L7 (2494.803, 80.01)-(2534.397, 80.01); L8 (2534.397, 80.01)-(2514.6, 114.3); L9 (2514.6, 3829.05)-(2514.6, 3771.9); L10 (2514.6, 3771.9)-(2494.803, 3806.19); L11 (2494.803, 3806.19)-(2534.397, 3806.19); L12 (2534.397, 3806.19)-(2514.6, 3771.9); L13 (114.3, 1943.1)-(171.45, 1943.1); L14 (171.45, 1943.1)-(137.16, 1962.897); L15 (137.16, 1962.897)-(137.16, 1923.303); L16 (137.16, 1923.303)-(171.45, 1943.1); L17 (4914.9, 1943.1)-(4857.75, 1943.1); L18 (4857.75, 1943.1)-(4892.04, 1962.897); L19 (4892.04, 1962.897)-(4892.04, 1923.303); L20 (4892.04, 1923.303)-(4857.75, 1943.1); L21 (1257.3, 114.3)-(1257.3, 77.724); L22 (1257.3, 3771.9)-(1257.3, 3808.476); L23 (3771.9, 114.3)-(3771.9, 77.724); L24 (3771.9, 3771.9)-(3771.9, 3808.476); L25 (171.45, 971.55)-(134.874, 971.55); L26 (4857.75, 971.55)-(4894.326, 971.55); L27 (171.45, 2914.65)-(134.874, 2914.65); L28 (4857.75, 2914.65)-(4894.326, 2914.65); 17 further points
    constraints: 56 end point, 8 point on line, 4 midpoint, 16 other
  sketch "_Closed_3"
